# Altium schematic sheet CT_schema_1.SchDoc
size 526 x 473 mm
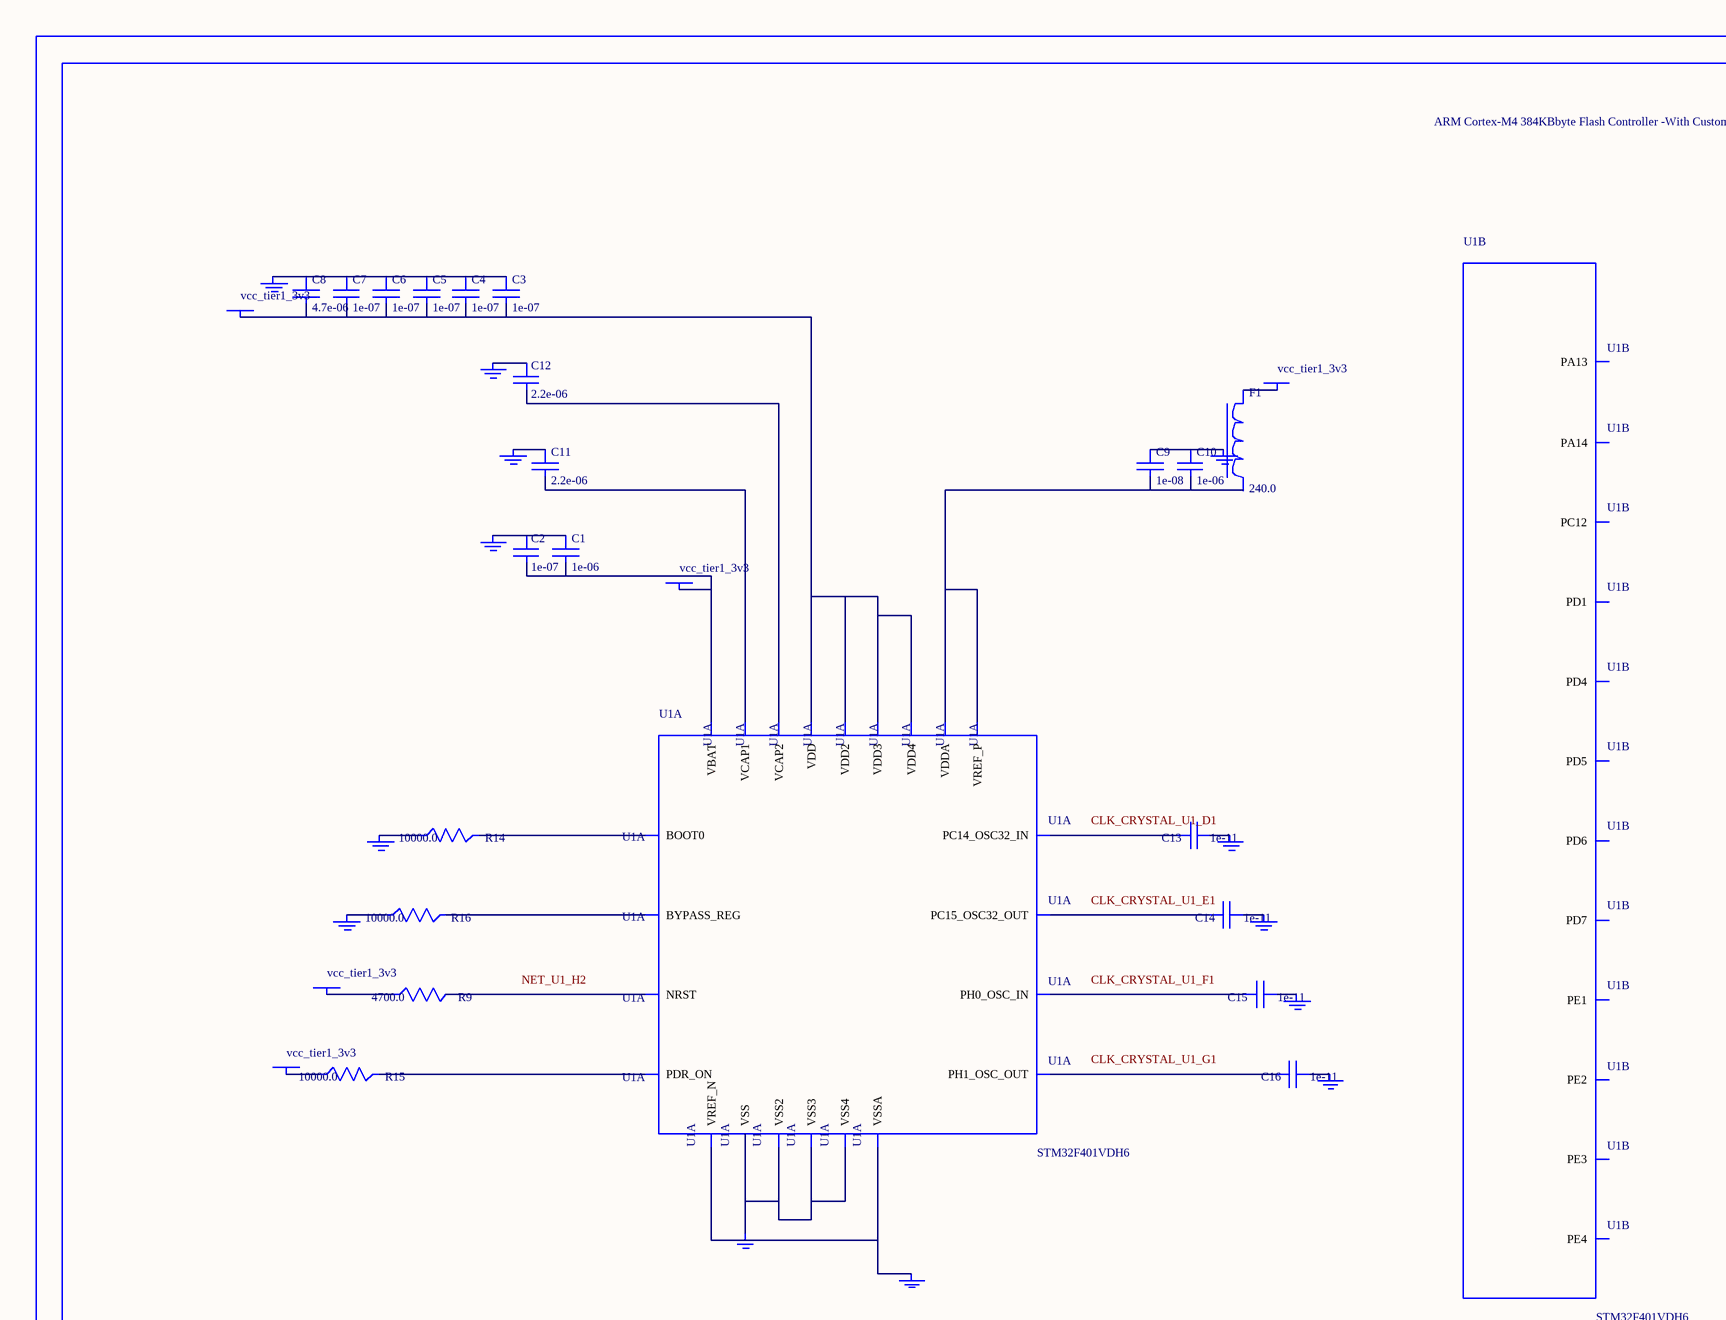
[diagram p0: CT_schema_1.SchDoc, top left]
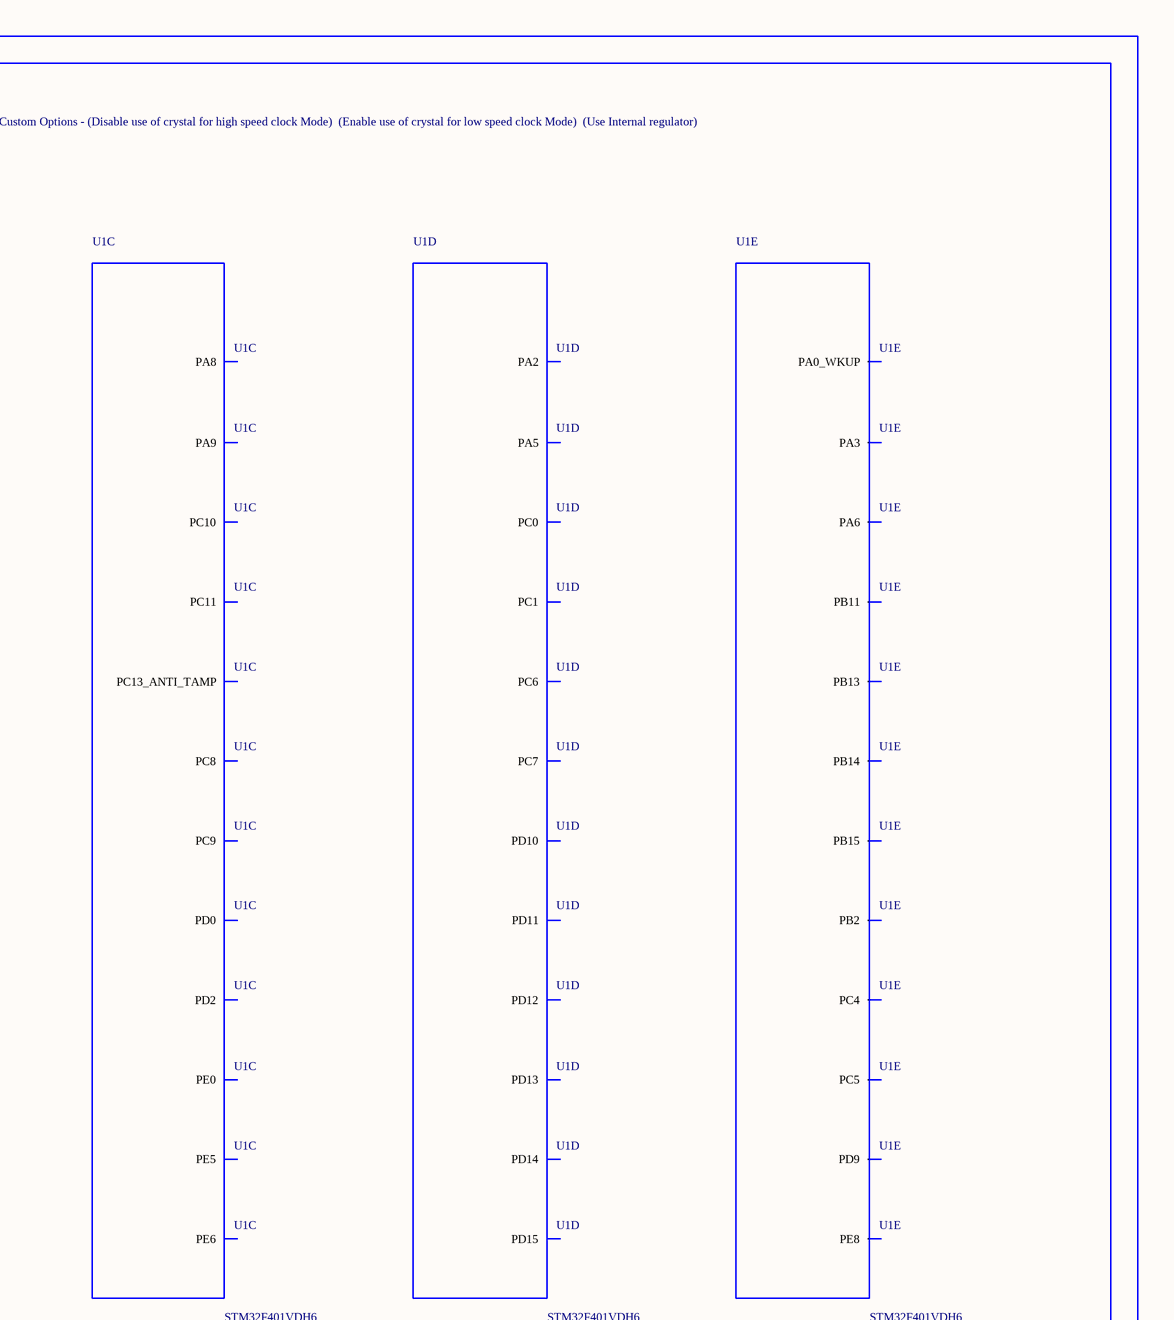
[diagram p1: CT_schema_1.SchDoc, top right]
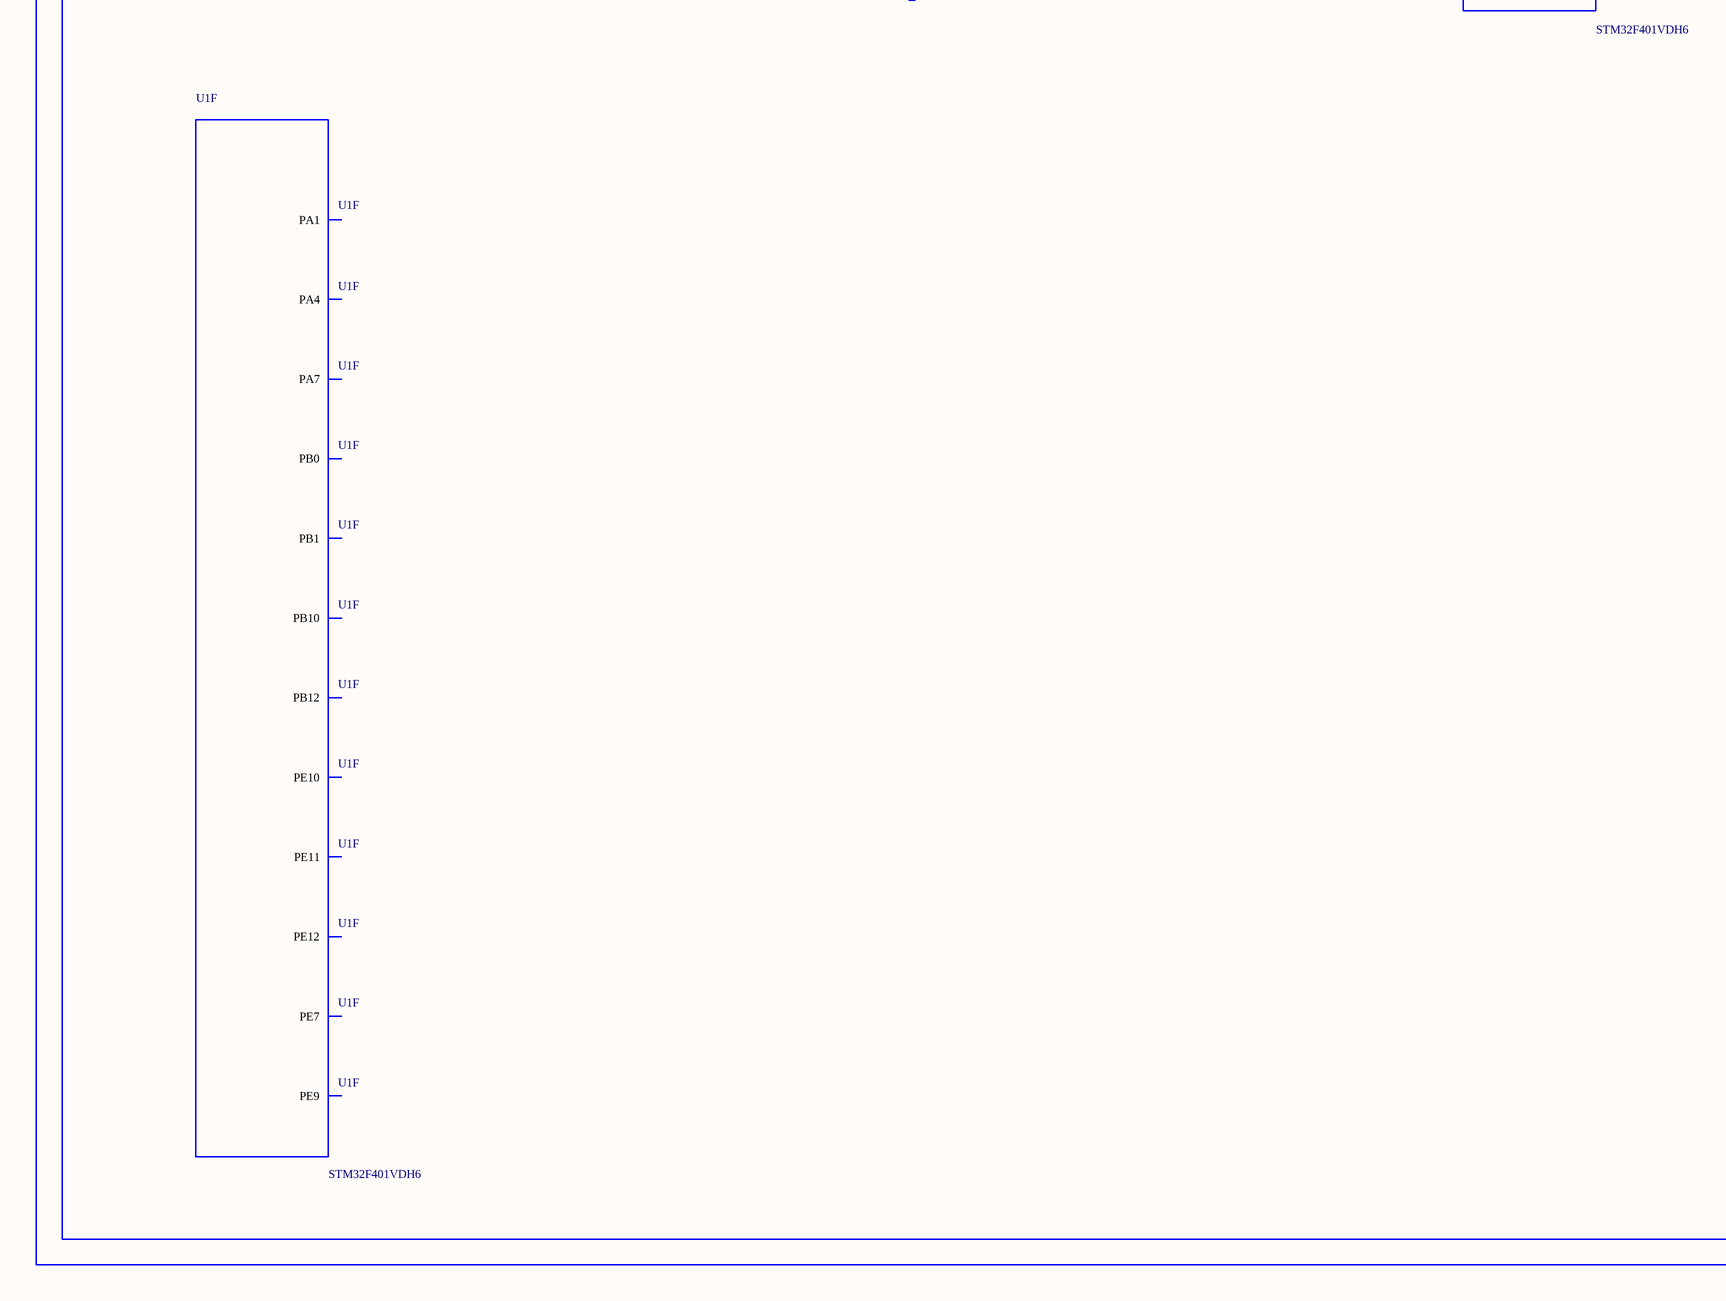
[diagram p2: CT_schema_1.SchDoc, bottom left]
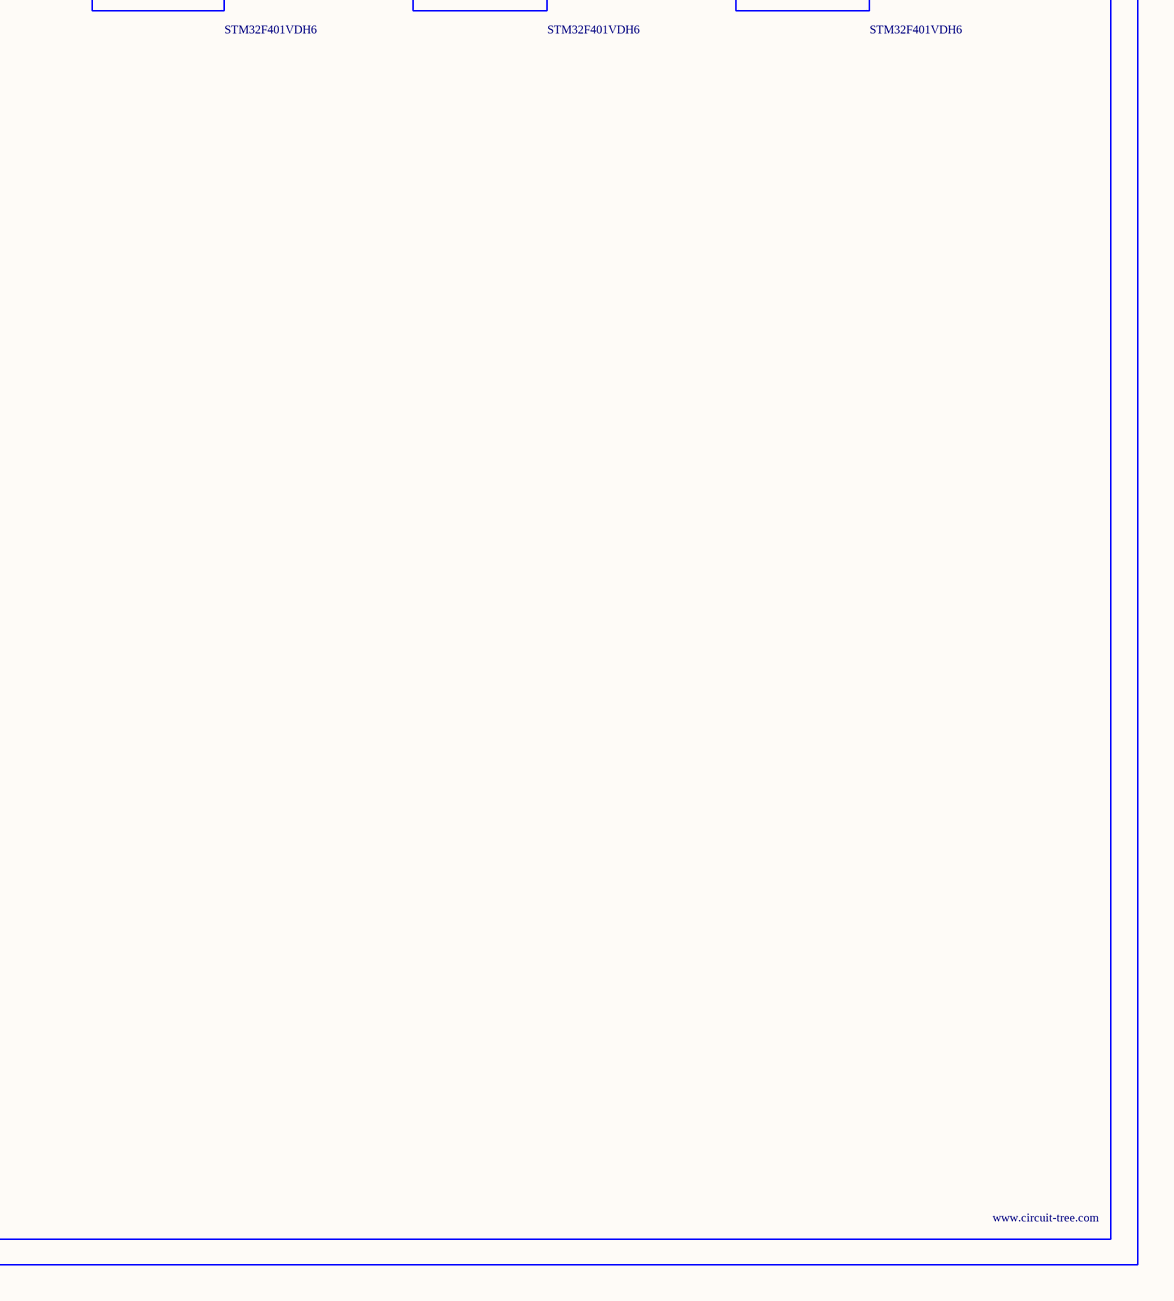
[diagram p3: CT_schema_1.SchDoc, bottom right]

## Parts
BORDER0  (no value)
C1  1e-06  [C0603]
C2  1e-07  [C0603]
C3  1e-07  [C0603]
C4  1e-07  [C0603]
C5  1e-07  [C0603]
C6  1e-07  [C0603]
C7  1e-07  [C0603]
C8  4.7e-06  [C0603]
C9  1e-08  [C0603]
C10  1e-06  [C0603]
C11  2.2e-06  [C0603]
C12  2.2e-06  [C0603]
C13  1e-11  [C0402]
C14  1e-11  [C0402]
C15  1e-11  [C0402]
C16  1e-11  [C0402]
F1  240.0  [L0603]
GND_INSTANCE_0_0  (no value)
GND_INSTANCE_0_1  (no value)
GND_INSTANCE_0_2  (no value)
GND_INSTANCE_0_3  (no value)
GND_INSTANCE_0_4  (no value)
GND_INSTANCE_0_5  (no value)
GND_INSTANCE_0_6  (no value)
GND_INSTANCE_0_7  (no value)
GND_INSTANCE_0_8  (no value)
GND_INSTANCE_0_9  (no value)
GND_INSTANCE_0_10  (no value)
GND_INSTANCE_0_11  (no value)
GND_INSTANCE_0_12  (no value)
POWER_INSTANCE_0_0  vcc_tier1_3v3
POWER_INSTANCE_0_1  vcc_tier1_3v3
POWER_INSTANCE_0_2  vcc_tier1_3v3
POWER_INSTANCE_0_3  vcc_tier1_3v3
POWER_INSTANCE_0_4  vcc_tier1_3v3
R9  4700.0  [R0603]
R14  10000.0  [R0603]
R15  10000.0  [R0603]
R16  10000.0  [R0603]
U1  STM32F401VDH6  [UFBGA100]  (parts A,B,C,D,E,F of 10)

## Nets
NetC1_1: C1.1 C2.1 GND_INSTANCE_0_0.0(GND)
NetC1_2: C1.2 C2.2 POWER_INSTANCE_0_0.0(PWR) U1.E2(VBAT)
NetC3_1: C3.1 C4.1 C5.1 C6.1 C7.1 C8.1 GND_INSTANCE_0_2.0(GND)
NetC3_2: C3.2 C4.2 C5.2 C6.2 C7.2 C8.2 POWER_INSTANCE_0_2.0(PWR) U1.C4(VDD) U1.G2(VDD4) U1.G11(VDD2) U1.G12(VDD3)
NetC9_1: C9.1 C10.1 GND_INSTANCE_0_1.0(GND)
NetC9_2: C9.2 C10.2 U1.L1(VREF_P) U1.M1(VDDA)
NetC11_1: C11.1 GND_INSTANCE_0_5.0(GND)
NetC11_2: C11.2 U1.L11(VCAP1)
NetC12_1: C12.1 GND_INSTANCE_0_6.0(GND)
NetC12_2: C12.2 U1.C11(VCAP2)
NetC13_1: C13.1 GND_INSTANCE_0_7.0(GND)
NetC13_2: C13.2 U1.D1(PC14_OSC32_IN)
NetC14_1: C14.1 GND_INSTANCE_0_8.0(GND)
NetC14_2: C14.2 U1.E1(PC15_OSC32_OUT)
NetC15_1: C15.1 GND_INSTANCE_0_9.0(GND)
NetC15_2: C15.2 U1.F1(PH0_OSC_IN)
NetC16_1: C16.1 GND_INSTANCE_0_10.0(GND)
NetC16_2: C16.2 U1.G1(PH1_OSC_OUT)
NetF1_1: F1.1 POWER_INSTANCE_0_1.0(PWR)
NetGND_INSTANCE_0_3_0: GND_INSTANCE_0_3.0(GND) R14.1
NetGND_INSTANCE_0_4_0: GND_INSTANCE_0_4.0(GND) R16.1
NetGND_INSTANCE_0_11_0: GND_INSTANCE_0_11.0(GND) U1.J1(VSSA) U1.K1(VREF_N)
NetGND_INSTANCE_0_12_0: GND_INSTANCE_0_12.0(GND) U1.D3(VSS) U1.F2(VSS4) U1.F11(VSS2) U1.F12(VSS3)
NetPOWER_INSTANCE_0_3_0: POWER_INSTANCE_0_3.0(PWR) R15.1
NetPOWER_INSTANCE_0_4_0: POWER_INSTANCE_0_4.0(PWR) R9.1
NetR9_2: R9.2 U1.H2(NRST)
NetR14_2: R14.2 U1.A4(BOOT0)
NetR15_2: R15.2 U1.H3(PDR_ON)
NetR16_2: R16.2 U1.E3(BYPASS_REG)

Not connected (* = marked no-connect by the designer): F1 2; U1 A1(PE3) A2(PE1) A5(PD7) A6(PD5) A10(PA14) A11(PA13) B1(PE4) B2(PE2) B6(PD6) B7(PD4) B9(PD1) B10(PC12) B11(PC10) C1(PC13_ANTI_TAMP) C2(PE5) C3(PE0) C8(PD2) C9(PD0) C10(PC11) D2(PE6) D10(PA9) D11(PA8) D12(PC9) E10(PC8) E11(PC7) E12(PC6) H1(PC0) H10(PD15) H11(PD14) H12(PD13) J2(PC1) J10(PD12) J11(PD11) J12(PD10) K3(PA2) K4(PA5) K5(PC4) K8(PD9) K9(PB11) K10(PB15) K11(PB14) K12(PB13) L2(PA0_WKUP) L3(PA3) L4(PA6) L5(PC5) L6(PB2) L7(PE8) L8(PE10) L9(PE12) L10(PB10) L12(PB12) M2(PA1) M3(PA4) M4(PA7) M5(PB0) M6(PB1) M7(PE7) M8(PE9) M9(PE11)

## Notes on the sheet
- Labels drawn without touching a wire or pin: CLK_CRYSTAL_U1_D1, CLK_CRYSTAL_U1_E1, CLK_CRYSTAL_U1_F1, CLK_CRYSTAL_U1_G1, NET_U1_H2

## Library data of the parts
BORDER0 = BORDER_PAGE0
C1 C10 = C0603C105K3RACTU
C2-C7 = 06035C104K4Z2A
C8 = GRM188R6YA475KE15D
C9 = 06035C103K4Z2A
C11 C12 = C0603C225K8RACTU
C13-C16 = C0402C100K3GACTU
F1 = Z0603C241ASMST
GND_INSTANCE_0_0-GND_INSTANCE_0_12 = GND
POWER_INSTANCE_0_0-POWER_INSTANCE_0_4 = PWR
R9 = RC0603JR-074K7L
R14-R16 = RC0603JR-0710KL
